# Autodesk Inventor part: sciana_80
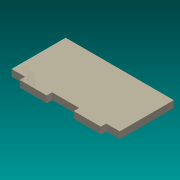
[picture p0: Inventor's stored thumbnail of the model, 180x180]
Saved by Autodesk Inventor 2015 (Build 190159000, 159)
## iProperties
Created: 2016-02
Part Number: sciana_80
Material: Generic
Document SubType Name: Modeling
Designer: Rafał
Density: 1 g/cm^3
Appearance: Light Beige
Author: Rafał
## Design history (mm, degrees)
sketch "Sketch1"
  geometry: L1 (0, 0)-(-80, 0); L2 (-80, 0)-(-80, 40); L3 (-80, 40)-(0, 40); L4 (0, 40)-(0, 0); L5 (-10, 0)-(-30, 0); L6 (-30, 0)-(-30, -4); L7 (-30, -4)-(-10, -4); L8 (-10, -4)-(-10, 0); L9 (-70, 0)-(-50, 0); L10 (-50, 0)-(-50, -4); L11 (-50, -4)-(-70, -4); L12 (-70, -4)-(-70, 0)
  constraints: 24 end point, 6 parallel, 3 horizontal, 3 perpendicular, 2 point on line
  dimensions: "d7" = 80 distance of L2.end L3.end; "d8" = 40 distance of L1.end L2.end; "d9" = 20 distance of L7.end L6.end; "d10" = 4 distance of L6.end L5.end; "d11" = 10 distance between parallel lines of L4 L8; "d12" = 20 distance of L10.end L11.end; "d13" = 10 distance between parallel lines of L2 L12
extrude "Extrusion1" new body sketch "Sketch1" distance "d14" = 5; taper "d15" = 0 deg
body "Solid1"
